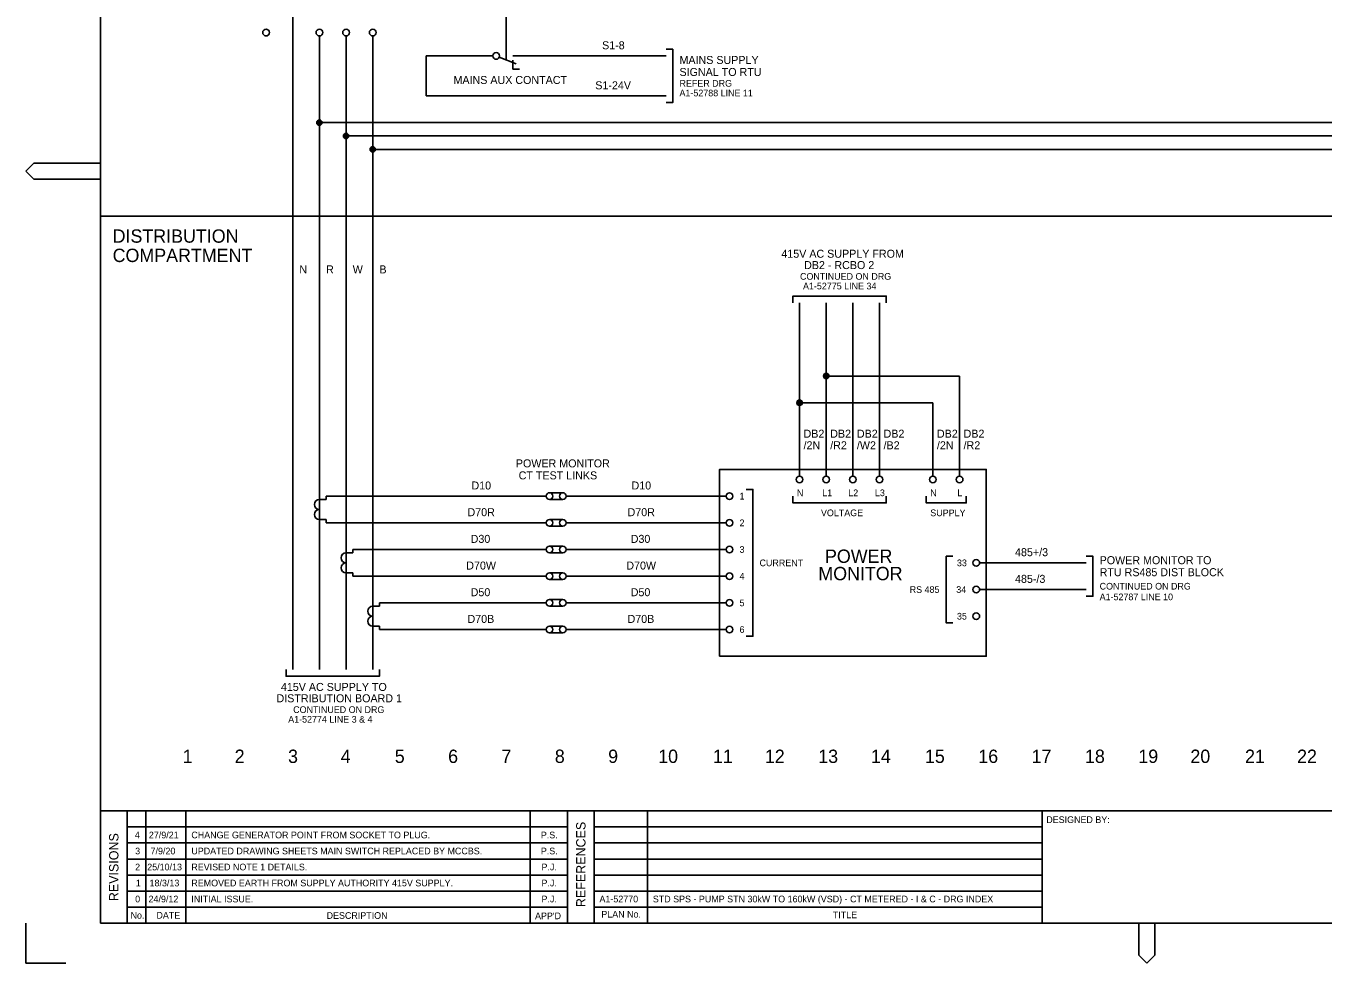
# Model space of a CAD drawing. Extents: x 0 to 841, y 0 to 594.
# Drawn here: x 0 to 486.2, y 0 to 351.2 of the extents above; entities that cross this region are included whole.
import ezdxf

# ---------------------------------------------------------------- set-up
doc = ezdxf.new("R2010")
doc.units = 0
for name, color, linetype in [('A1BORDER', 7, 'Continuous'), ('Level 1', 7, 'Continuous'), ('Level 10', 7, 'Continuous')]:
    doc.layers.add(name, color=color, linetype=linetype)

msp = doc.modelspace()

# ---------------------------------------------------------------- linework, layer by layer
at = {"layer": 'A1BORDER'}
for p, q in [((28, 581), (28, 15)), ((3, 299.76), (0, 296.76)), ((3, 293.76), (0, 296.76)), ((28, 299.76), (3, 299.76)), ((28, 293.76), (3, 293.76)), ((28, 57), (829, 57)), ((38, 15), (38, 57)), ((45, 15), (45, 57)), ((60, 15), (60, 57)), ((189, 15), (189, 57)), ((203, 15), (203, 57)), ((213, 15), (213, 57)), ((233, 15), (233, 57)), ((381, 15), (381, 57)), ((203, 51), (38, 51)), ((213, 51), (381, 51)), ((203, 45), (38, 45)), ((213, 45), (381, 45)), ((203, 39), (38, 39)), ((213, 39), (381, 39)), ((203, 33), (38, 33)), ((213, 33), (381, 33)), ((38, 27), (203, 27)), ((213, 27), (381, 27)), ((203, 21), (38, 21)), ((213, 21), (381, 21)), ((0, 0), (0, 15)), ((829, 15), (28, 15)), ((417.19, 15), (417.19, 3)), ((423.19, 15), (423.19, 3)), ((0, 0), (15, 0)), ((417.19, 3), (420.19, 0)), ((423.19, 3), (420.19, 0))]:
    msp.add_line(p, q, dxfattribs=at)
at = {"layer": 'Level 1'}
for p, q in [((100, 110), (100, 557.5)), ((180, 338.5), (180, 362.5)), ((110, 347.5), (110, 110)), ((120, 347.5), (120, 110)), ((130, 347.5), (130, 110)), ((175, 340), (150, 340)), ((150, 340), (150, 325)), ((185, 340), (240, 340)), ((150, 325), (240, 325)), ((109.01, 315.1), (110.99, 315.1)), ((109.02, 314.8), (110.98, 314.8)), ((109.08, 315.4), (110.92, 315.4)), ((109.13, 314.5), (110.87, 314.5)), ((109.29, 315.7), (110.71, 315.7)), ((109.4, 314.2), (110.6, 314.2)), ((110, 316), (110, 316)), ((660, 315), (110, 315)), ((119.01, 310.1), (120.99, 310.1)), ((119.02, 309.8), (120.98, 309.8)), ((119.08, 310.4), (120.92, 310.4)), ((119.13, 309.5), (120.87, 309.5)), ((119.29, 310.7), (120.71, 310.7)), ((119.4, 309.2), (120.6, 309.2)), ((120, 311), (120, 311)), ((120, 310), (670, 310)), ((129.01, 305.1), (130.99, 305.1)), ((129.02, 304.8), (130.98, 304.8)), ((129.08, 305.4), (130.92, 305.4)), ((129.13, 304.5), (130.87, 304.5)), ((129.29, 305.7), (130.71, 305.7)), ((129.4, 304.2), (130.6, 304.2)), ((130, 306), (130, 306)), ((130, 305), (680, 305)), ((28, 280), (829, 280)), ((290, 182.5), (290, 247.5)), ((300, 247.5), (300, 182.5)), ((310, 247.5), (310, 182.5)), ((320, 247.5), (320, 182.5)), ((350, 220), (300, 220)), ((350, 182.5), (350, 220)), ((340, 210), (290, 210)), ((340, 210), (340, 182.5)), ((201.25, 176.29), (196.25, 176.29)), ((112.5, 173.75), (112.5, 175.04)), ((195, 175.04), (112.5, 175.04)), ((201.25, 173.79), (196.25, 173.79)), ((262.5, 175), (202.5, 175)), ((112.5, 166.25), (112.5, 165)), ((201.25, 166.25), (196.25, 166.25)), ((195, 165), (112.5, 165)), ((201.25, 163.75), (196.25, 163.75)), ((262.5, 165), (202.5, 165)), ((201.25, 156.29), (196.25, 156.29)), ((122.5, 153.75), (122.5, 155.04)), ((195, 155.04), (122.5, 155.04)), ((201.25, 153.79), (196.25, 153.79)), ((262.5, 155), (202.5, 155)), ((122.5, 146.25), (122.5, 145)), ((201.25, 146.25), (196.25, 146.25)), ((357.5, 150), (397.5, 150)), ((195, 145), (122.5, 145)), ((201.25, 143.75), (196.25, 143.75)), ((262.5, 145), (202.5, 145)), ((201.25, 136.29), (196.25, 136.29)), ((357.5, 140), (397.5, 140)), ((132.5, 133.75), (132.5, 135.04)), ((195, 135.04), (132.5, 135.04)), ((201.25, 133.79), (196.25, 133.79)), ((262.5, 135), (202.5, 135)), ((132.5, 126.26), (132.5, 125)), ((195, 125), (132.5, 125)), ((201.25, 126.25), (196.25, 126.25)), ((201.25, 123.75), (196.25, 123.75)), ((262.5, 125), (202.5, 125))]:
    msp.add_line(p, q, dxfattribs=at)
for points in [[(240, 342.5), (242.5, 342.5), (242.5, 322.5), (240, 322.5)], [(287.5, 247.5), (287.5, 250), (322.5, 250), (322.5, 247.5)], [(270, 177.5), (272.5, 177.5), (272.5, 122.5), (270, 122.5)], [(287.5, 175), (287.5, 172.5), (322.5, 172.5), (322.5, 175)], [(337.5, 175), (337.5, 172.5), (352.5, 172.5), (352.5, 175)], [(347.5, 152.5), (345, 152.5), (345, 127.5), (347.5, 127.5)], [(397.5, 152.5), (400, 152.5), (400, 137.5), (397.5, 137.5)], [(97.5, 110), (97.5, 107.5), (132.5, 107.5), (132.5, 110)]]:
    msp.add_lwpolyline(points, dxfattribs=at)
msp.add_lwpolyline([(260, 115), (360, 115), (360, 185), (260, 185)], close=True, dxfattribs=at)
for centre, radius in [((90, 348.75), 1.25), ((110, 348.75), 1.25), ((120, 348.75), 1.25), ((130, 348.75), 1.25), ((110, 315), 1), ((120, 310), 1), ((130, 305), 1), ((196.25, 175.04), 1.25), ((201.25, 175.04), 1.25), ((196.25, 165), 1.25), ((201.25, 165), 1.25), ((196.25, 155.04), 1.25), ((201.25, 155.04), 1.25), ((196.25, 145), 1.25), ((201.25, 145), 1.25), ((196.25, 135.04), 1.25), ((201.25, 135.04), 1.25), ((196.25, 125), 1.25), ((201.25, 125), 1.25)]:
    msp.add_circle(centre, radius, dxfattribs=at)
at = {"layer": 'Level 10'}
for p, q in [((177.41, 339.54), (183.75, 337)), ((182.5, 340), (185, 340)), ((182.5, 338.37), (182.5, 335)), ((182.5, 335), (185, 335)), ((299, 220), (299, 220)), ((299.1, 219.56), (299.1, 220.44)), ((299.4, 219.2), (299.4, 220.8)), ((299.7, 219.05), (299.7, 220.95)), ((300, 219), (300, 220.99)), ((300.3, 219.05), (300.3, 220.95)), ((300.6, 219.2), (300.6, 220.8)), ((300.9, 219.56), (300.9, 220.44)), ((289, 210), (289, 210)), ((289.1, 209.56), (289.1, 210.44)), ((289.4, 209.2), (289.4, 210.8)), ((289.7, 209.05), (289.7, 210.95)), ((290, 209), (290, 210.99)), ((290.3, 209.05), (290.3, 210.95)), ((290.6, 209.2), (290.6, 210.8)), ((290.9, 209.56), (290.9, 210.44)), ((110, 173.75), (112.5, 173.75)), ((110, 166.25), (112.5, 166.25)), ((120, 153.75), (122.5, 153.75)), ((120, 146.25), (122.5, 146.25)), ((130, 133.75), (132.5, 133.75)), ((130, 126.26), (132.5, 126.26))]:
    msp.add_line(p, q, dxfattribs=at)
for centre, radius in [((176.25, 340), 1.25), ((300, 220), 1), ((290, 210), 1), ((290, 181.25), 1.25), ((300, 181.25), 1.25), ((310, 181.25), 1.25), ((320, 181.25), 1.25), ((340, 181.25), 1.25), ((350, 181.25), 1.25), ((263.75, 175), 1.25), ((263.75, 165), 1.25), ((263.75, 155), 1.25), ((356.25, 150), 1.25), ((263.75, 145), 1.25), ((356.25, 140), 1.25), ((263.75, 135), 1.25), ((356.25, 130), 1.25), ((263.75, 125), 1.25)]:
    msp.add_circle(centre, radius, dxfattribs=at)
for centre in [(110, 171.88), (110, 168.12), (120, 151.88), (120, 148.12), (130, 131.88), (130, 128.12)]:
    msp.add_arc(centre, 1.87, 90, 270, dxfattribs=at)

# ---------------------------------------------------------------- texts
at = {"layer": 'A1BORDER'}
for s, p in [('DESIGNED BY:', (382.5, 52.5)), ('PLAN No.', (215.69, 17.06)), ('No.', (39.21, 16.65)), ('DATE', (48.92, 16.65)), ('DESCRIPTION', (112.71, 16.57)), ("APP'D", (190.85, 16.44)), ('TITLE', (302.5, 16.81))]:
    msp.add_text(s, height=2.5, dxfattribs=at).set_placement(p)
for s, p in [('REFERENCES', (209.76, 20.96)), ('REVISIONS', (34.68, 23.2))]:
    msp.add_text(s, height=3.5, rotation=90, dxfattribs=at).set_placement(p)
at = {"layer": 'Level 1'}
for s, height, p in [('S1-8', 3, (215.97, 342.5)), ('SIGNAL TO RTU', 3, (245, 332.5)), ('MAINS SUPPLY', 3, (245, 337)), ('MAINS AUX CONTACT', 3, (160.28, 329.5)), ('REFER DRG', 2.5, (245, 328.49)), ('S1-24V', 3, (213.43, 327.5)), ('A1-52788 LINE 11', 2.5, (245, 324.87)), ('DISTRIBUTION', 5, (32.5, 270)), ('COMPARTMENT', 5, (32.5, 262.76)), ('415V AC SUPPLY FROM', 3, (283.19, 264.37)), ('DB2 - RCBO 2', 3, (291.7, 260.12)), ('N', 3, (102.5, 258.5)), ('R', 3, (112.5, 258.5)), ('W', 3, (122.5, 258.5)), ('B', 3, (132.5, 258.5)), ('CONTINUED ON DRG', 2.5, (290.18, 256.12)), ('A1-52775 LINE 34', 2.5, (291.3, 252.5)), ('DB2', 3, (291.5, 196.92)), ('DB2', 3, (301.5, 196.92)), ('DB2', 3, (311.5, 196.92)), ('DB2', 3, (321.5, 196.92)), ('DB2', 3, (341.5, 196.92)), ('DB2', 3, (351.5, 196.92)), ('/2N', 3, (291.5, 192.58)), ('/R2', 3, (301.5, 192.58)), ('/W2', 3, (311.5, 192.58)), ('/B2', 3, (321.5, 192.58)), ('/2N', 3, (341.5, 192.58)), ('/R2', 3, (351.5, 192.58)), ('POWER MONITOR', 3, (183.66, 185.79)), ('D10', 3, (167.01, 177.5)), ('CT TEST LINKS', 3, (184.71, 181.29)), ('D10', 3, (227.01, 177.5)), ('1', 2.5, (267.5, 173.75)), ('N', 2.5, (289, 175)), ('L1', 2.5, (298.51, 175)), ('L2', 2.5, (308.26, 175)), ('L3', 2.5, (318.26, 175)), ('N', 2.5, (339, 175)), ('L', 2.5, (349.13, 175)), ('D70R', 3, (165.52, 167.5)), ('D70R', 3, (225.52, 167.5)), ('2', 2.5, (267.5, 163.75)), ('VOLTAGE', 2.5, (298.03, 167.5)), ('SUPPLY', 2.5, (339.02, 167.5)), ('D30', 3, (166.71, 157.5)), ('D30', 3, (226.71, 157.5)), ('3', 2.5, (267.5, 153.75)), ('485+/3', 3, (370.78, 152.5)), ('CURRENT', 2.5, (275, 148.75)), ('POWER', 5, (299.54, 150)), ('33', 2.5, (349.01, 148.75)), ('POWER MONITOR TO', 3, (402.5, 149.5)), ('D70W', 3, (165.07, 147.5)), ('D70W', 3, (225.07, 147.5)), ('4', 2.5, (267.5, 143.75)), ('MONITOR', 5, (297.05, 143.5)), ('RTU RS485 DIST BLOCK', 3, (402.5, 145)), ('RS 485', 2.5, (331.29, 138.75)), ('34', 2.5, (348.76, 138.75)), ('485-/3', 3, (370.78, 142.5)), ('CONTINUED ON DRG', 2.5, (402.5, 140)), ('D50', 3, (166.71, 137.5)), ('D50', 3, (226.71, 137.5)), ('5', 2.5, (267.5, 133.75)), ('A1-52787 LINE 10', 2.5, (402.5, 136)), ('D70B', 3, (165.52, 127.5)), ('D70B', 3, (225.52, 127.5)), ('35', 2.5, (349.01, 128.75)), ('6', 2.5, (267.5, 123.75)), ('415V AC SUPPLY TO', 3, (95.58, 101.99)), ('DISTRIBUTION BOARD 1', 3, (93.93, 97.74)), ('A1-52774 LINE 3 & 4', 2.5, (98.32, 90.12)), ('CONTINUED ON DRG', 2.5, (100.18, 93.74)), ('1', 5, (58.76, 75)), ('2', 5, (78.26, 75)), ('3', 5, (98.26, 75)), ('4', 5, (118.01, 75)), ('5', 5, (138.26, 75)), ('6', 5, (158.26, 75)), ('7', 5, (178.26, 75)), ('8', 5, (198.26, 75)), ('9', 5, (218.26, 75)), ('10', 5, (237.01, 75)), ('11', 5, (257.51, 75)), ('12', 5, (277.01, 75)), ('13', 5, (297.01, 75)), ('14', 5, (316.76, 75)), ('15', 5, (337.01, 75)), ('16', 5, (357.01, 75)), ('17', 5, (377.01, 75)), ('18', 5, (397.01, 75)), ('19', 5, (417.01, 75)), ('20', 5, (436.52, 75)), ('21', 5, (457.01, 75)), ('22', 5, (476.52, 75)), ('4', 2.5, (40.82, 46.75)), ('27/9/21', 2.5, (46.09, 46.75)), ('CHANGE GENERATOR POINT FROM SOCKET TO PLUG.', 2.5, (62, 46.75)), ('P.S.', 2.5, (193.02, 46.75)), ('3', 2.5, (40.94, 40.75)), ('7/9/20', 2.5, (46.72, 40.75)), ('UPDATED DRAWING SHEETS MAIN SWITCH REPLACED BY MCCBS.', 2.5, (62, 40.75)), ('P.S.', 2.5, (193.02, 40.75)), ('2', 2.5, (40.94, 34.75)), ('25/10/13', 2.5, (45.47, 34.75)), ('REVISED NOTE 1 DETAILS.', 2.5, (62, 34.75)), ('P.J.', 2.5, (193.26, 34.75)), ('1', 2.5, (41.19, 28.75)), ('18/3/13', 2.5, (46.34, 28.75)), ('REMOVED EARTH FROM SUPPLY AUTHORITY 415V SUPPLY.', 2.5, (62, 28.75)), ('P.J.', 2.5, (193.26, 28.75)), ('0', 2.5, (40.94, 22.75)), ('24/9/12', 2.5, (45.97, 22.75)), ('INITIAL ISSUE.', 2.5, (62, 22.75)), ('P.J.', 2.5, (193.26, 22.75)), ('A1-52770', 2.5, (215, 22.75)), ('STD SPS - PUMP STN 30kW TO 160kW (VSD) - CT METERED - I & C - DRG INDEX', 2.5, (235, 22.75))]:
    msp.add_text(s, height=height, dxfattribs=at).set_placement(p)

doc.saveas('drawing.dxf')
